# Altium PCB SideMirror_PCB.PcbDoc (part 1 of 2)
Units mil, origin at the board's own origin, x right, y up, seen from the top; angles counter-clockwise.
Board outline 2391.73 x 2364.18 mil, 2 copper layers (Top Layer, Bottom Layer), stack 62 mil thick; 77 components, 73 nets, 281 pads, 345 vias.
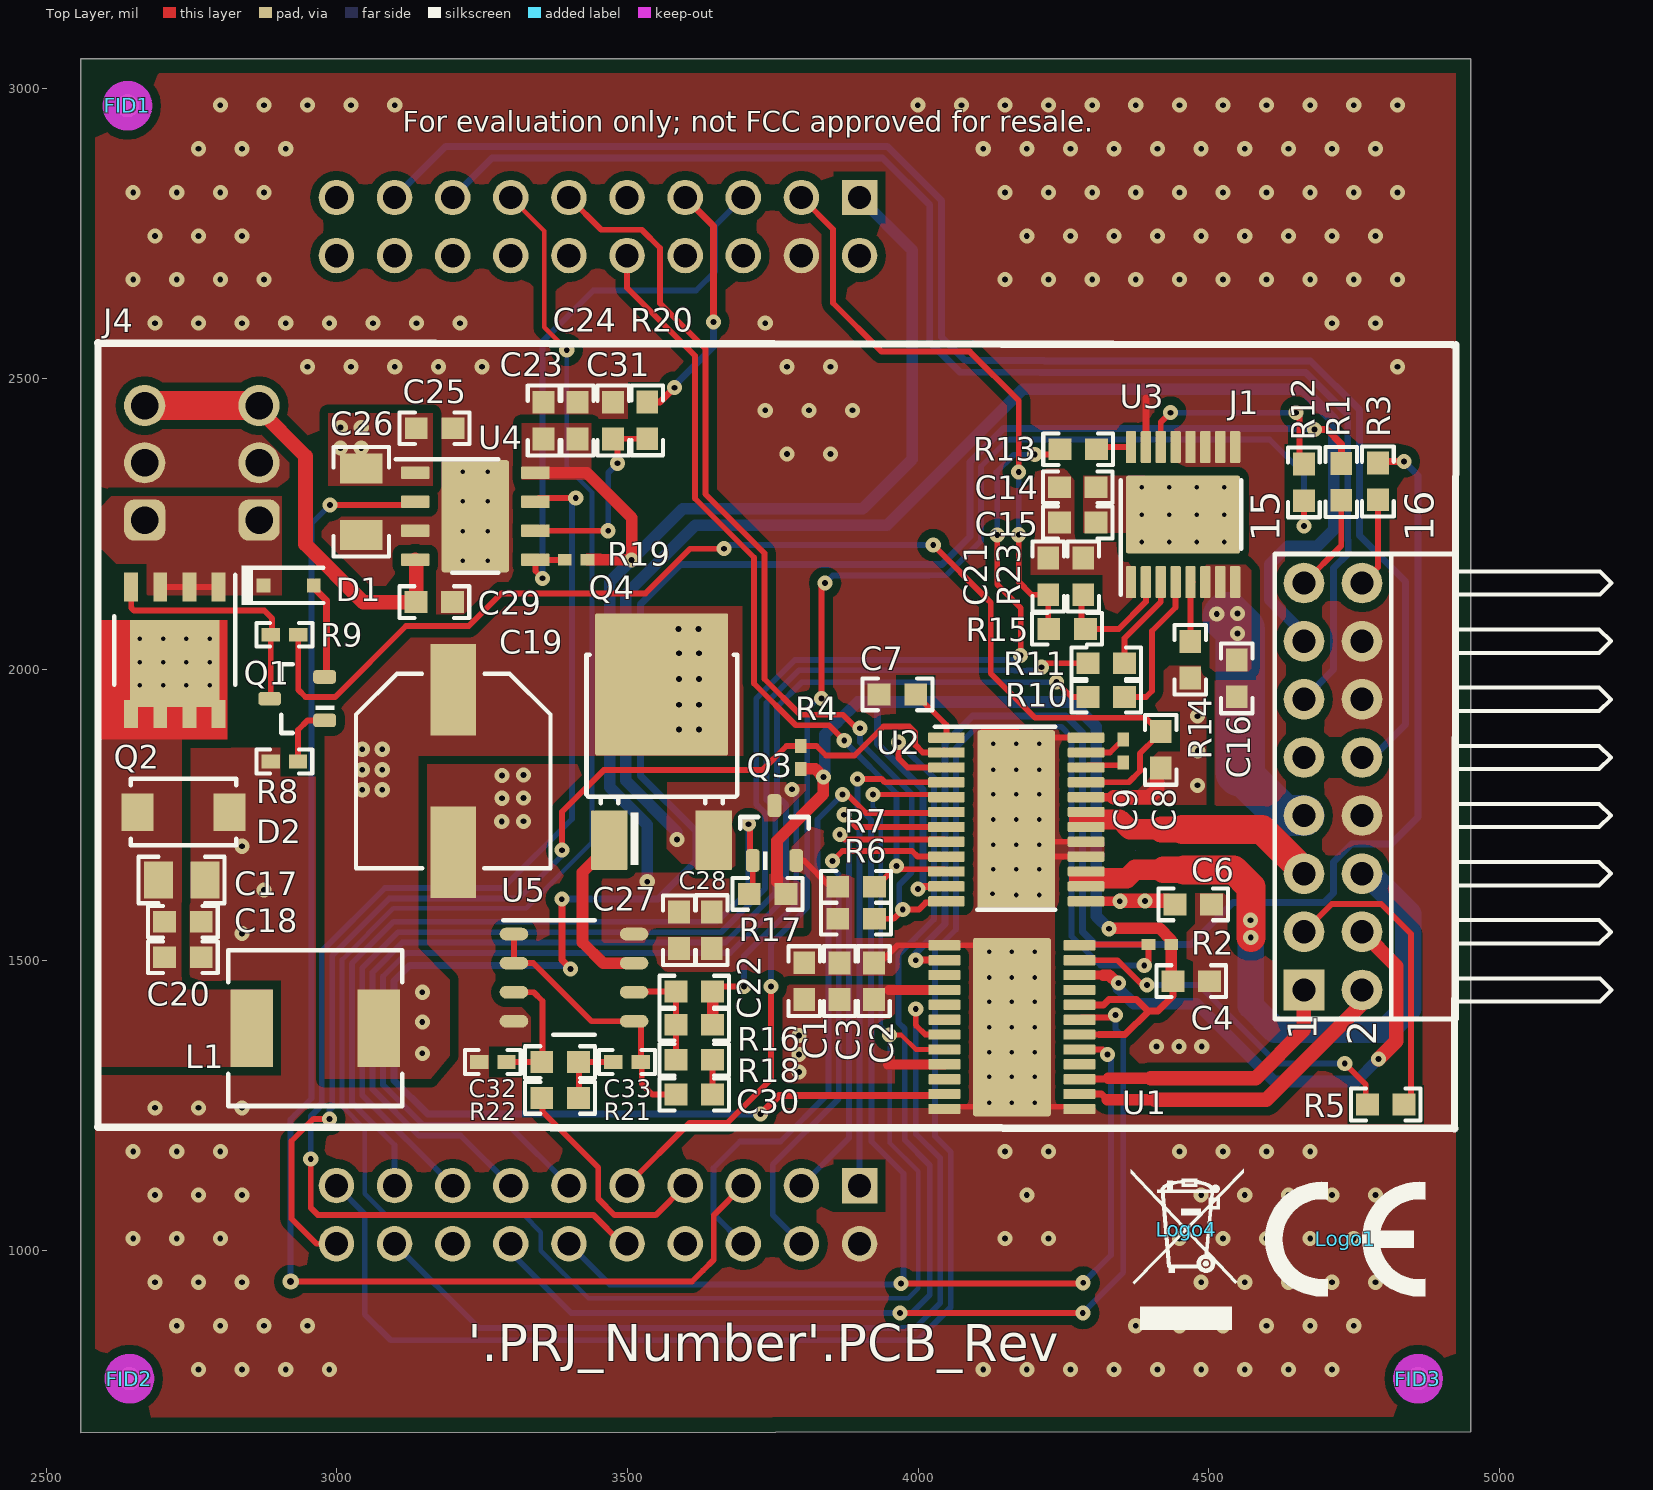
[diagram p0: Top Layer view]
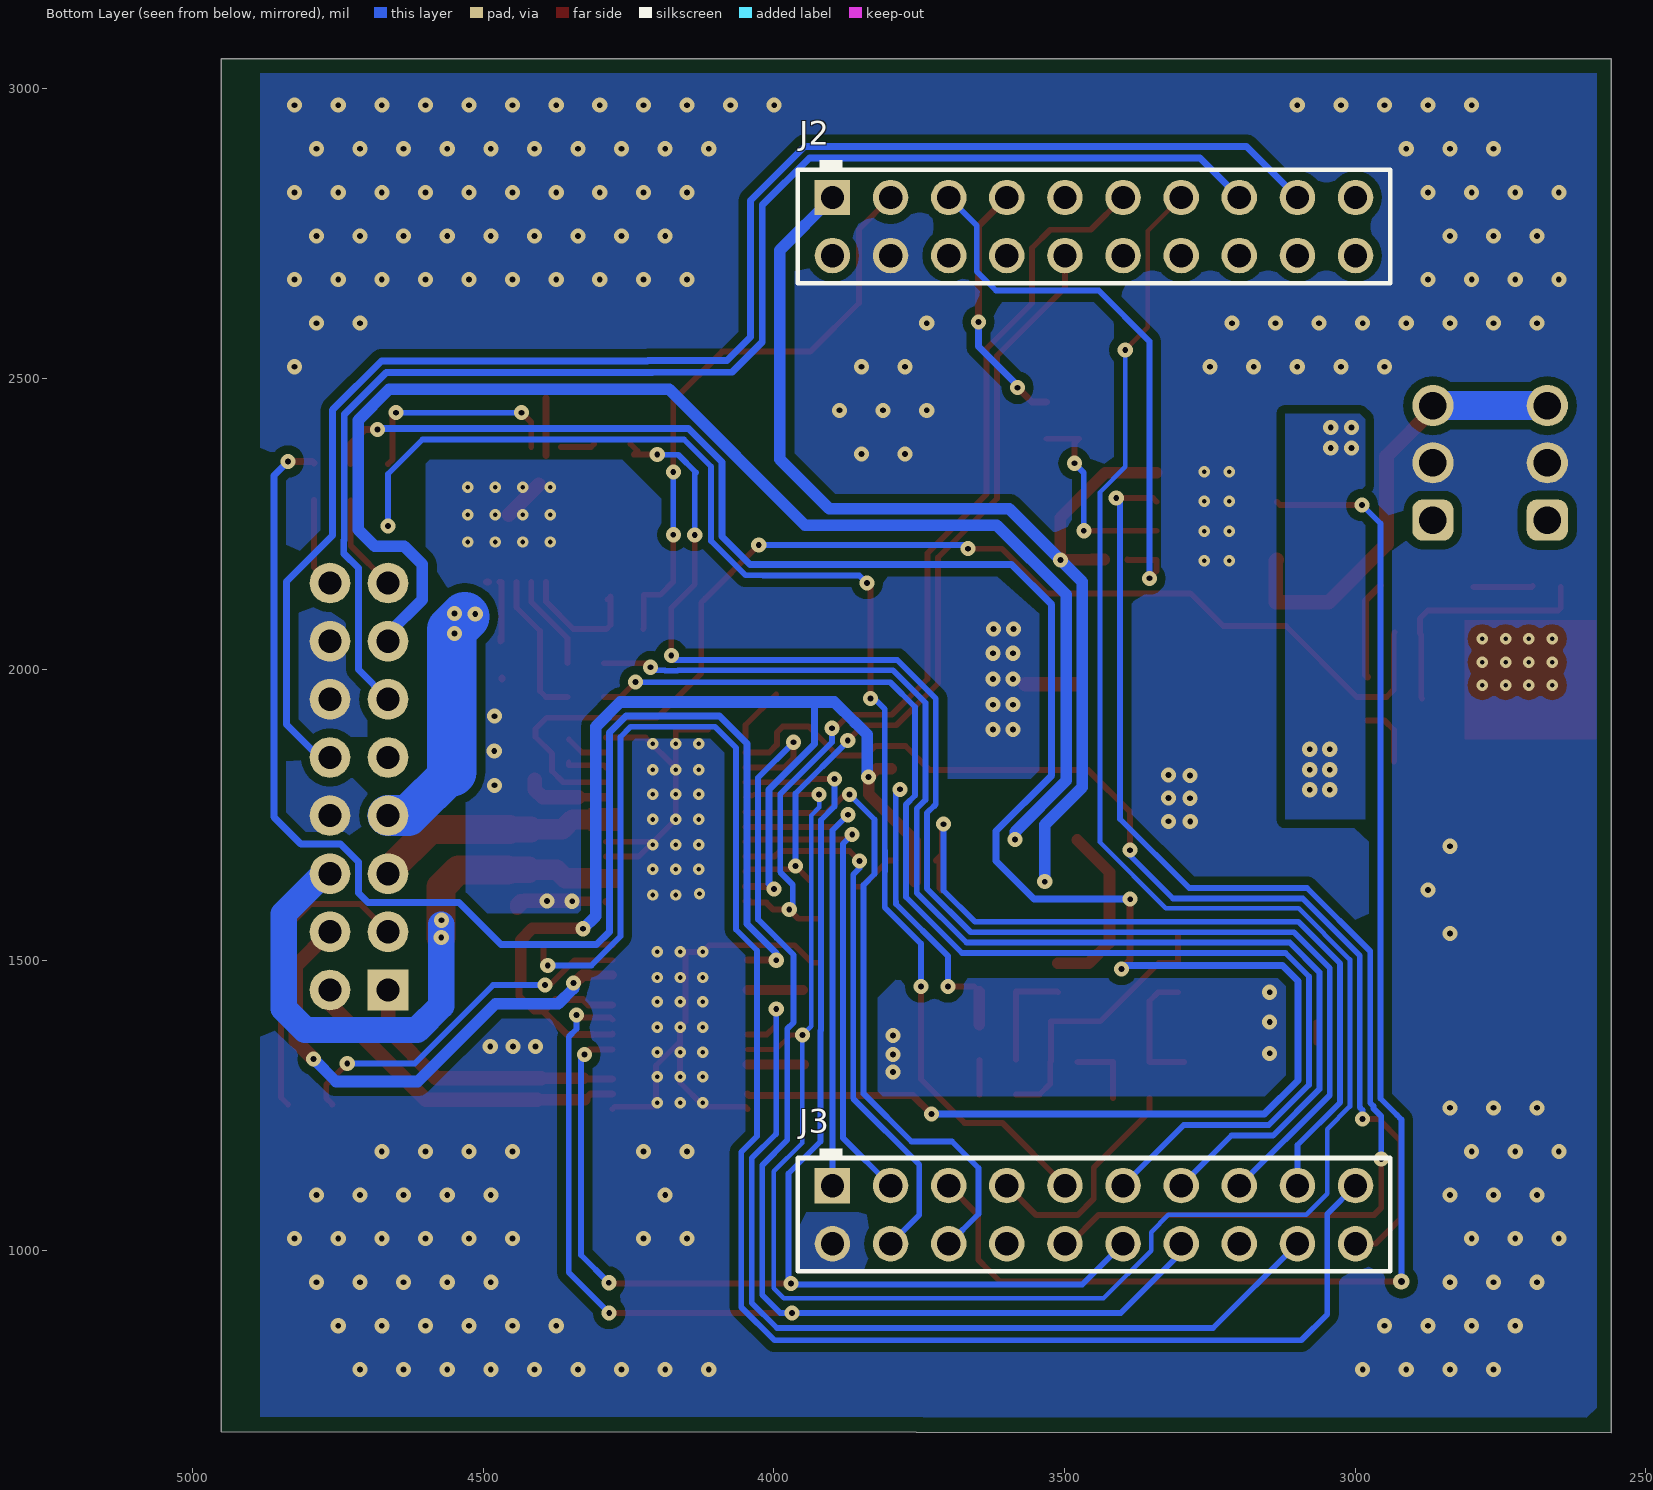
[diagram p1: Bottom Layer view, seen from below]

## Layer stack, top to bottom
Top Solder: solder mask 0.4, Solder Resist, Dk 3.5
Top Layer: signal copper 1.4
Dielectric1: core 59.2, FR-4, Dk 4.8
Bottom Layer: signal copper 1.4
Bottom Solder: solder mask 0.4, Solder Resist, Dk 3.5

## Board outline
2559.06,687 4950.79,688.98 4950.79,3051.18 2559.06,3051.18

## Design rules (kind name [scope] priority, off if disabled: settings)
AcuteAngle [All] p1: minimum=4.50000000000000E+0001 checktracksonly=FALSE
AssemblyTestPointUsage [All] p1: valid=2
BoardOutlineClearance BoardOutlineClearance_MountingHoles [OnCopper and InComponentClass('Mounting Holes')] p1: gap=39.37 ignorepadtopadclearanceinfootprint=FALSE
BoardOutlineClearance BoardOutlineClearance_Poly [OnCopper and IsPoly] p2: gap=25 ignorepadtopadclearanceinfootprint=FALSE
BoardOutlineClearance [OnCopper and Not InComponentClass('Logo') and not InComponentClass('FiducialMark') and not InRegion(1000,500,4000,800) and not InPoly] p3: gap=60 ignorepadtopadclearanceinfootprint=FALSE
Clearance Clearance_Keepouts [((IsTrack Or IsArc) And Not InPoly) And IsFree and IsKeepOut vs ((IsTrack Or IsArc) And Not InPoly) And IsFree and IsKeepOut] p1: gap=0 ignorepadtopadclearanceinfootprint=FALSE
Clearance Clearance_Poly [InPolygon] p2: gap=15 ignorepadtopadclearanceinfootprint=TRUE
Clearance Clearance_FiducialMark [IsKeepOut and InComponentClass('FiducialMark') vs IsPad and InComponentClass('FiducialMark')] p3: gap=0 ignorepadtopadclearanceinfootprint=FALSE
Clearance [All] p4: gap=7.87 ignorepadtopadclearanceinfootprint=TRUE
ComponentClearance ComponentClearance_MountingHoles_FiducialMarks [InComponentClass('Mounting Holes') vs InComponentClass('FiducialMark')] p1: gap=50 collisioncheckmode=3 verticalgap=10 showdistances=FALSE
ComponentClearance ComponentClearance_Shunt [InComponentClass('Header') vs InComponentClass('Shunt')] p2: gap=0 collisioncheckmode=3 verticalgap=0 showdistances=FALSE
ComponentClearance ComponentClearance_Logo [InComponentClass('Logo')] p3: gap=50 collisioncheckmode=3 verticalgap=10 showdistances=FALSE
ComponentClearance ComponentClearance_ScrewToNut [(HasFootprint('NY PMS 440 0025 PH')) vs (HasFootprint('Keystone_1902C'))] p4: gap=5 collisioncheckmode=3 verticalgap=10 showdistances=FALSE
ComponentClearance ComponentClearance_MountingHoles [InComponentClass('Mounting Holes')] p5: gap=250 collisioncheckmode=3 verticalgap=100000 showdistances=FALSE
ComponentClearance ComponentClearance_SmallPassives [HasFootprint('0201*') or HasFootprint('0402*') or HasFootprint('0508') or HasFootprint('0603*') or HasFootprint('0612') or HasFootprint('0805*') or HasFootprint('0815*') or HasFootprint('0830*') or HasFootprint('1206*') or HasFootprint('1210*') or HasFootprint('1808*') or HasFootprint('1812*') or HasFootprint('1825*') or HasFootprint('2010*') or HasFootprint('2220*') or HasFootprint('2225*') or HasFootprint('2512*') or HasFootprint('2728*') or HasFootprint('3518*') vs HasFootprint('0201*') or HasFootprint('0402*') or HasFootprint('0508') or HasFootprint('0603*') or HasFootprint('0612') or HasFootprint('0805*') or HasFootprint('0815*') or HasFootprint('0830*') or HasFootprint('1206*') or HasFootprint('1210*') or HasFootprint('1808*') or HasFootprint('1812*') or HasFootprint('1825*') or HasFootprint('2010*') or HasFootprint('2220*') or HasFootprint('2225*') or HasFootprint('2512*') or HasFootprint('2728*') or HasFootprint('3518*')] p6: gap=14.96 collisioncheckmode=3 verticalgap=10 showdistances=FALSE
ComponentClearance ComponentClearance_THtoSMT [IsThruComponent vs IsSMTComponent] p7: gap=40 collisioncheckmode=3 verticalgap=30 showdistances=FALSE
ComponentClearance ComponentClearance_THtoTH [IsThruComponent vs IsThruComponent] p8: gap=30 collisioncheckmode=3 verticalgap=30 showdistances=FALSE
ComponentClearance [All] p9: gap=30 collisioncheckmode=3 verticalgap=10 showdistances=FALSE
DiffPairsRouting [All] p1: maxlimit=100 minlimit=10 mostfreqgap=10 toplayer_minwidth=15 toplayer_maxwidth=15 toplayer_prefwidth=15 bottomlayer_minwidth=15 bottomlayer_maxwidth=15 bottomlayer_prefwidth=15 maxuncoupledlength=1000
FabricationTestPointUsage TestPointUsage [All] p1: valid=2 allowmultiple=FALSE
FabricationTestpoint Testpoint [All] p1: side=3 testpointundercomponent=TRUE minsize=40 maxsize=100 preferedsize=60 minholesize=0 maxholesize=40 preferedholesize=32 testpointgrid=1 allowsidetop=TRUE allowsidebottom=TRUE usegrid=TRUE gridtolerance=0.01
FanoutControl Fanout_LCC [IsLCC] p1: bgadir=Out bgaviamode=Centered fanoutstyle=Auto fanoutdirection=Alternating viagrid=1 // Fanout_LCC (Default Rule)
FanoutControl Fanout_BGA [IsBGA] p2: bgadir=Out bgaviamode=Centered fanoutstyle=Auto fanoutdirection=Alternating viagrid=1 // Fanout_BGA (Default Rule)
FanoutControl Fanout_Default [All] p4: bgadir=Out bgaviamode=Centered fanoutstyle=Auto fanoutdirection=Alternating viagrid=1 // Fanout_Default (Default Rule)
FanoutControl Fanout_Small [(CompPinCount < 5)] p5: bgadir=Out bgaviamode=Centered fanoutstyle=Auto fanoutdirection=OutThenIn viagrid=1 // Fanout_Small (Default Rule)
HoleSize [All] p1: absolutevalues=TRUE maxlimit=251 minlimit=7.87 maxpercent=80.000 minpercent=20.000
MinimumAnnularRing MinimumAnnularRing_ThermalPadVias [IsVia and InAnyComponent] p1: minimumring=5.91
MinimumAnnularRing [All] p2: minimumring=7.87
MinimumSolderMaskSliver MinimumSolderMaskSliver_Logo [InComponentClass('Logo') vs InComponentClass('Logo')] p1: minsoldermaskwidth=0.7
MinimumSolderMaskSliver [All] p2: minsoldermaskwidth=2.5
PlaneConnect [All] p1: planeconnectstyle=Relief reliefexpansion=10 reliefentries=4 reliefconductorwidth=10 reliefairgap=10
PolygonConnect [All] p1: connectstyle=Direct reliefconductorwidth=10 reliefentries=4 polygonreliefangle="90 Angle" airgapwidth=10
RoutingVias ThermalPadVias [IsVia and InAnyComponent] p1: holewidth=7.87 width=19.68 viastyle="Through Hole" minholewidth=7.87 minwidth=19.68 maxholewidth=12.99 maxwidth=23.62
RoutingVias [All] p2: holewidth=16 width=34 viastyle="Through Hole" minholewidth=7.87 minwidth=26 maxholewidth=40 maxwidth=65
SilkToBoardRegionClearance [Not ((IsComment or IsDesignator) And (Hide <> 'False')) and not InRegion(1000,500,4000,800)] p1:
SilkToSilkClearance SilkToSilkClearance_Pb-FreeLogo [(HasFootprint('Pb-Free_Overlay_Medium') OR HasFootprint('Pb-Free_Overlay_Small')) vs (HasFootprint('Pb-Free_Overlay_Medium') OR HasFootprint('Pb-Free_Overlay_Small'))] p1: silktosilkclearance=0
SilkToSilkClearance [All] p2: silktosilkclearance=2.5
SilkToSolderMaskClearance SilkToComponentPadClearance [(IsPad or IsFill or IsRegion) and InAnycomponent] p1: minsilkscreentomaskgap=5 clearancetoexposedcopper=TRUE
SilkToSolderMaskClearance "Silk to Solder Mask Opening" [All] p2: minsilkscreentomaskgap=3.94 clearancetoexposedcopper=FALSE
SolderMaskExpansion [All] p1: expansion=1.97
UnRoutedNet [All] p1: checkbadconnections=TRUE
Width [All] p1: maxlimit=100 minlimit=6 preferedwidth=10 checkconnectedcopper=TRUE
14 further rules are at their usual default settings.

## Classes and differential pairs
component class AssemblyNote: ZZ1 ZZ2 ZZ3 ZZ4
component class FiducialMark: FID1 FID2 FID3
component class SideMirror_Hardware: FID1 FID2 FID3 J1 J2 J3 Logo1 Logo3 Logo4 ZZ1 ZZ2 ZZ3 ZZ4
component class Header: J1
component class SideMirror_Drivers: C1 C2 C3 C4 C6 C7 C8 C9 R1 R2 R3 R4 R5 R6 R7 U1 U2
component class SideMirror_Logic_TLIN1028: C14 C15 C16 C17 C18 C19 C20 C21 C22 C23 C24 C25 C26 C27 C28 C29 C30 C31 C32 C33 C34 D1 D2 J4 L1 Q1 Q2 Q3 Q4 R8 R9 R10 R11 R12 R13 R14 R15 R16 R17 R18 R19 R20 R21 R22 R23 U3 U4 U5

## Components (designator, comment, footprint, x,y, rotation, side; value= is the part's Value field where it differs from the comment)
C1 "UMK107AB7105KA-T" 0603 3804,1464.01 r90 top value=1uF
C2 "UMK107AB7105KA-T" 0603 3924,1464 r90 top value=1uF
C3 "C0603C104J5RACTU" 0603 3864.81,1464 r270 top value=0.1uF
C4 "GRM188R70J103KA01D" 0603 4470,1464 r0 top value=0.01uF
C6 "C0603C104J5RACTU" 0603 4473.19,1596 r180 top value=0.1uF
C7 "GRM185R60J105KE26D" 0603 3964.5,1957.31 r180 top value=1uF
C8 "UMK107AB7105KA-T" 0603 4417.41,1861.87 r90 top value=1uF
C9 "Capacitor" 0402L 4353,1860 r90 top value=0.047uF
C14 "GRM188R71H104KA93D" 0603 4274.59,2313.57 r180 top value=0.1uF
C15 "GRM188R71H224KAC4D" 0603 4274.59,2253.01 r180 top value=0.22uF
C16 "C0603X223K5RACTU" 0603 4548,1984.8 r270 top value=0.022uF
C17 "GRM21BR71H105KA12L" 0805_HV 2733,1638 r0 top value=1uF
C18 "C1608X7R1H104K080AA" 0603 2735.1,1566 r0 top value=0.1uF
C19 "EEE-FK1J470P" SM_RADIAL_F 3200.18,1825.48 r270 top locked value=47uF
C20 "C1608X7R1H103K080AA" 0603 2735.1,1504.99 r0 top value=0.01uF
C21 "0603ZC101KAT2A" 0603 4224.03,2160.24 r270 top value=100pF
C22 "0603ZC100KAT2A" 0603 3615,1446 r180 top value=10pF
C23 "GRM188Z71A106MA73D" 0603 3355.56,2428.5 r270 top value=10uF
C24 "C0603C104K4RACTU" 0603 3414,2428.5 r270 top value=0.1uF
C25 "C1608X7R1H104K080AA" 0603 3168,2415.1 r180 top value=0.1uF
C26 "CGA5L3X5R1H106M160AB" 1206 3042,2288.78 r270 top value=10uF
C27 "GRM188Z71C475KE21D" 0603 3588.61,1551.69 r270 top value=4.7uF
C28 "GCM188R71C104KA37J" 0603 3645,1551.74 r270 top value=0.1uF
C29 "C0603C221K5RACTU" 0603 3167.72,2116.14 r0 top value=220pF
C30 "GCM188R71H472KA37D" 0603 3615,1269 r180 top value=4700pF
C31 "06033C101KAT2A" 0603 3475.24,2428.5 r270 top value=100pF
C32 "CGA2B3X8R1H103K050BB" 0402 3268.31,1324.79 r180 top value=0.01uF
C33 "GRM155R71H223KA12D" 0402 3499.21,1324.79 r180 top value=0.022uF
D1 "1N4148WS-7-F" SOD-323 2916.86,2144.69 r0 top value=75V
D2 "SMAJ36CA" SMA_Bi 2736,1754.92 r0 top value=36V
FID1 "Fiducial" Fiducial10-20 2639.69,2970 r0 top
FID2 "Fiducial" Fiducial10-20 2643,780 r0 top
FID3 "Fiducial" Fiducial10-20 4860,780 r0 top
J1 "TSW-108-08-G-D-RA" GPSI16 4713.78,1798.82 r90 top locked
J2 "SSQ-110-23-F-D" Samtec_SSQ-110-23-F-D 3449.21,2762.2 r180 bottom locked
J3 "SSQ-110-23-F-D" Samtec_SSQ-110-23-F-D 3449.21,1062.2 r180 bottom locked
J4 "1770898" Phoenix_1770898 2767.72,2355.71 r90 top
L1 "SRP6540-2R2M" SRP6540 2962.51,1383 r0 top value=2.2uH
Logo1 "CE Mark" CE_Mark_5mm 4734.69,1020 r0 top
Logo3 "FCC disclaimer" FCC_disclaimer 2350,3380 r0 top
Logo4 "WEEE logo" WEEE_Minimum 4461,1036.37 r0 top
Q1 "BC846BLT1G" SOT-23 2931.73,1950 r180 top value="65 V"
Q2 "SI7634BDP-T1-E3" PowerPAK_SO-8 2721.1,2032.8 r270 top value=30V
Q3 "FMMT495TA" SOT-23 3752.79,1718.76 r90 top value="150 V"
Q4 "NJVMJD122T4G" DPAK 3558.63,1840.55 r90 top locked value="100 V"
R1 "CRCW0603200RJNEA" 0603 4728,2322.83 r270 top value=200
R2 "Resistor" 0402L 4416,1527 r0 top value=10k
R3 "CRCW0603200RJNEA" 0603 4791,2323.6 r270 top value=200
R4 "Resistor" 0402L 3798,1848.82 r270 top value=10k
R5 "CRCW0603200RJNEA" 0603 4804.45,1251.64 r0 top value=200
R6 "RC0603FR-07680RL" 0603 3893.21,1571.26 r0 top value=680
R7 "RC0603FR-07680RL" 0603 3893.21,1626.26 r0 top value=680
R8 "CRCW040210K0JNED" 0402 2909.62,1842 r180 top value=10k
R9 "CRCW040210K0JNED" 0402 2910,2060 r0 top value=10k
R10 "CRCW060315K0FKEA" 0603 4323.56,1953 r0 top value=15.0k
R11 "CRCW060315K0FKEA" 0603 4323.56,2010.99 r0 top value=15.0k
R12 "CRCW060315K0FKEA" 0603 4663.78,2322 r90 top value=15.0k
R13 "CRCW060315K0FKEA" 0603 4275.29,2379 r0 top value=15.0k
R14 "CRCW060320K0FKEA" 0603 4468.03,2017 r90 top value=20.0k
R15 "CRCW060315K0FKEA" 0603 4256.25,2070 r0 top value=15.0k
R16 "RT0603DRE0710K1L" 0603 3615,1389 r0 top value=10.1k
R17 "RC0603FR-074K7L" 0603 3740.98,1614 r0 top value=4.70k
R18 "CRCW0603499RFKEA" 0603 3615,1328.74 r180 top value=499
R19 "Resistor" 0402L 3411.61,2189.29 r0 top value=10k
R20 "CRCW06031K00FKEA" 0603 3534.12,2428.7 r270 top value=1.00k
R21 "CRCW060378K7FKEA" 0603 3384,1263 r0 top value=78.7k
R22 "CRCW060314K7FKEA" 0603 3383.91,1324.79 r180 top value=14.7k
R23 "ERJ-3EKF1001V" 0603 4284.05,2160.24 r270 top value=1.00k
U1 "DRV8906QPWPRQ1" PWP0024N_N 4161.42,1384.84 r180 top
U2 "DRV8873SPWPRQ1" PWP0024J_M 4168.79,1742.13 r0 top
U3 "TPS1HB16BQPWPTQ1" PWP0016M_N 4455.8,2266.69 r90 top
U4 "TLIN1028DDA" DDA0008G_L 3238.19,2263.78 r0 top
U5 "LM2904QDRQ1" D0008A_L 3408,1470 r0 top
ZZ1 "This Assembly Note is for PCB labels only" AssemblyNoteLabel 185,3938 r0 top
ZZ2 "These assemblies are ESD sensitive, ESD precautions shall be observed." AssemblyNote 185,3829.11 r0 top
ZZ3 "These assemblies must be clean and free from flux and all contaminants. Use of no clean flux is not acceptable." AssemblyNote 185,3740.56 r0 top
ZZ4 "These assemblies must comply with workmanship standards IPC-A-610 Class 2, unless otherwise specified." AssemblyNote 185,3652 r0 top

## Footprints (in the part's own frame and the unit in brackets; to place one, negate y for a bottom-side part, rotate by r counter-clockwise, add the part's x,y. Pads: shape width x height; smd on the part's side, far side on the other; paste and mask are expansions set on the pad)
0402 [mm] "0402 from SM-752 data"
  rect 0.8x0.6 smd: 1(-0.6,0) 2(0.6,0)
  silkscreen extent -1.22,-0.52 1.22,0.52, body extent -0.55,-0.3 0.55,0.3, height 0.6
0402L [mm] "0402 from SM-752 data"
  rect 0.6x0.5 smd: 1(-0.5,0) 2(0.5,0)
  body extent -0.55,-0.3 0.55,0.3, height 0.6
0603 [mm] "0603 from SM-752 data"
  rect 1x0.95 smd: 1(-0.8,0) 2(0.8,0)
  silkscreen extent -1.52,-0.69 1.52,0.69, body extent -0.87,-0.47 0.87,0.47, height 1
0805_HV [mil] "0805 with 30mil clearance between pads"
  rect 50x63 smd: 1(-40,0) 2(40,0)
  silkscreen extent -74,-40 74,40, body extent -43,-29 43,29, height 57
1206 [mm] "1206 from SM-752 data"
  rect 1.3x1.85 smd: 1(-1.45,0) 2(1.45,0)
  silkscreen extent -2.4,-1.21 2.4,1.21, body extent -1.7,-0.9 1.7,0.9, height 1.35
AssemblyNote [mil] "Assembly Note"
AssemblyNoteLabel [mil] "Assembly Note for PCB Labels"
CE_Mark_5mm [mil] "Minimum text height for CE Mark"
  silkscreen extent -138,-98 138,98
D0008A_L [mm] "SOIC, 8-Leads, Body 4.9x3.9mm, Pitch 1.27mm, IPC High Density"
  oval 1.25x0.55 smd: 1(-2.625,1.905) 2(-2.625,0.635) 3(-2.625,-0.635) 4(-2.625,-1.905) 5(2.625,-1.905) 6(2.625,-0.635) 7(2.625,0.635) 8(2.625,1.905)
  silkscreen extent -3.1,-2.5 0.9,2.5, body extent -3,-2.45 3,2.45, height 1.63
DDA0008G_L [mm] "SOIC, 8-Leads, Body 4.9x3.9mm, Pitch 1.27mm, Exposed Pad, IPC High Density"
  rrect18% 1.25x0.55 smd: 1(-2.625,1.905) 2(-2.625,0.635) 3(-2.625,-0.635) 4(-2.625,-1.905) 5(2.625,-1.905) 6(2.625,-0.635) 7(2.625,0.635) 8(2.625,1.905)
  rrect7% 2.95x4.9 smd paste-1.5 mask-1.5: 9(0,0)
  rrect4% 2.29x3.1 on Top Solder: 9(0,0)
  rrect4% 2.29x3.1 on Top Paste: 9(0,0)
  silkscreen extent -3.47,-2.48 1,2.5, body extent -2.98,-2.45 2.98,2.45, height 1.55
DPAK [mm] "D-PAK, 3-Pads, Body 6.22x6.73mm (max), TO-252AA using nominal STEP model"
  rrect6% 2.6x1.6 smd: 1(-3.4,2.28) 3(-3.4,-2.28)
  rrect2% 6.2x5.8 smd paste-2.9: 4(3.4,0)
  silkscreen extent -4.5,-3.3 4.7,3.28, body extent -3.86,-3.29 5.84,3.29, height 2.48
FCC_disclaimer [mil]
Fiducial10-20 [mm]
  round 1 smd mask+0.5: 1(0,0)
  Top Layer keep-out circle w1.178: c0,0 r0.5
GPSI16 [mil] "Samtec Right Angle Header, pins flipped from convention"
  rect 70x70 hole 40: 1(-350,50)
  round 70 hole 40: 2(-350,-50) 3(-250,50) 4(-250,-50) 5(-150,50) 6(-150,-50) 7(-50,50) 8(-50,-50) 9(50,50) 10(50,-50) 11(150,50) 12(150,-50) 13(250,50) 14(250,-50) 15(350,50) 16(350,-50)
  silkscreen extent -400,-479 400,100, body extent -400,-440 400,63, height 219
Phoenix_1770898 [mm] "Terminal Block, 3 Pos, 2.5mm, R/A, TH"
  rrect50% 1.8x1.8 hole 1.2: 1(-2.5,-2.5) 1(-2.5,2.5)
  round 1.8 hole 1.2: 2(0,2.5) 2(0,-2.5) 3(2.5,-2.5) 3(2.5,2.5)
  body extent -3.1,-4.7 5,5.3, height 5
PowerPAK_SO-8 [mil] "Vishay PowerPAK SO-8, Body 5.3x6.0mm (max), Pitch 1.27mm, IPC Medium Density"
  rect 50x24 smd mask+2.99: 1(-109.5,75) 2(-109.5,25) 3(-109.5,-25) 4(-109.5,-75)
  rect 48x24 smd mask+2.99: 5(109.5,-75) 8(109.5,75)
  rect 48x24 smd paste-12 mask+2.99: 6(109.5,-25) 7(109.5,25)
  rect 150x154 smd paste-75 mask+2.99: 9(22.5,0)
  silkscreen extent -130,-104 59,104, body extent -121,-102 121,102, height 43
PWP0016M_N [mm] "TSOP, 16-Leads, Body 5x4.4mm, Pitch 0.65mm, Thermal Pad 2.41x3.29 mm, IPC Medium Density"
  rrect22% 1.4x0.45 smd: 1(-2.95,2.275) 2(-2.95,1.625) 3(-2.95,0.975) 4(-2.95,0.325) 5(-2.95,-0.325) 6(-2.95,-0.975) 7(-2.95,-1.625) 8(-2.95,-2.275) 9(2.95,-2.275) 10(2.95,-1.625) 11(2.95,-0.975) 12(2.95,-0.325) 13(2.95,0.325) 14(2.95,0.975) 15(2.95,1.625) 16(2.95,2.275)
  rrect6% 3.4x5 smd paste-1.7 mask-1.7: 17(0,0)
  rrect4% 2.78x3.37 on Top Solder: 17(0,0)
  rrect4% 2.78x3.37 on Top Paste: 17(0,0)
  silkscreen extent -3.5,-2.55 1.5,2.73, body extent -3.21,-2.5 3.21,2.5, height 0.99
PWP0024J_M [mm] "TSOP, 24-Leads, Body 7.9x4.5mm (max), Pitch 0.65mm, IPC Low Density"
  rrect22% 1.6x0.45 smd: 1(-3.05,3.575) 2(-3.05,2.925) 3(-3.05,2.275) 4(-3.05,1.625) 5(-3.05,0.975) 6(-3.05,0.325) 7(-3.05,-0.325) 8(-3.05,-0.975) 9(-3.05,-1.625) 10(-3.05,-2.275) 11(-3.05,-2.925) 12(-3.05,-3.575) 13(3.05,-3.575) 14(3.05,-2.925) 15(3.05,-2.275) 16(3.05,-1.625) 17(3.05,-0.975) 18(3.05,-0.325) 19(3.05,0.325) 20(3.05,0.975) 21(3.05,1.625) 22(3.05,2.275) 23(3.05,2.925) 24(3.05,3.575)
  rrect6% 3.4x7.8 smd paste-2 mask-2: 25(0,0)
  rrect3% 3.2x5.26 on Top Solder mask+0.085: 25(0,0)
  rrect3% 3.2x5.26 on Top Paste mask+0.085: 25(0,0)
  silkscreen extent -3.55,-3.95 1.7,4.05, body extent -3.21,-3.9 3.21,3.9, height 1.2
PWP0024N_N [mm] "TSOP-24"
  rrect22% 1.4x0.45 smd: 1(-2.95,3.575) 2(-2.95,2.925) 3(-2.95,2.275) 4(-2.95,1.625) 5(-2.95,0.975) 6(-2.95,0.325) 7(-2.95,-0.325) 8(-2.95,-0.975) 9(-2.95,-1.625) 10(-2.95,-2.275) 11(-2.95,-2.925) 12(-2.95,-3.575) 13(2.95,-3.575) 14(2.95,-2.925) 15(2.95,-2.275) 16(2.95,-1.625) 17(2.95,-0.975) 18(2.95,-0.325) 19(2.95,0.325) 20(2.95,0.975) 21(2.95,1.625) 22(2.95,2.275) 23(2.95,2.925) 24(2.95,3.575)
  rrect6% 3.4x7.8 smd paste-2 mask-2: 25(0,0)
  body extent -3.21,-3.9 3.21,3.9, height 1.2
Samtec_SSQ-110-23-F-D [mm] "Receptacle, 2.54mm, 10x2, TH"
  rect 1.55x1.55 hole 1.02: 1(-11.43,1.27)
  round 1.55 hole 1.02: 2(-11.43,-1.27) 3(-8.89,1.27) 4(-8.89,-1.27) 5(-6.35,1.27) 6(-6.35,-1.27) 7(-3.81,1.27) 8(-3.81,-1.27) 9(-1.27,1.27) 10(-1.27,-1.27) 11(1.27,1.27) 12(1.27,-1.27) 13(3.81,1.27) 14(3.81,-1.27) 15(6.35,1.27) 16(6.35,-1.27) 17(8.89,1.27) 18(8.89,-1.27) 19(11.43,1.27) 20(11.43,-1.27)
  silkscreen extent -12.95,-2.48 12.95,2.9, body extent -12.95,-2.48 12.95,2.48, height 8.51
SM_RADIAL_F [mm] "8 x 10.2mm:  Panasonic F"
  rect 4x2 smd: 1(-3.55,0) 2(3.55,0)
  silkscreen extent -4.25,-4.25 4.25,4.25, body extent -4.25,-4.25 4.25,4.25, height 10.5
SMA_Bi [mm] "SMD, 2-Leads, Body 4.275x2.575mm"
  rect 1.4x1.64 smd: 1(-2.015,0) 2(2.015,0)
  silkscreen extent -2.3,-1.45 2.3,1.45, body extent -2.52,-1.45 2.52,1.45, height 2.65
SOD-323 [mm] "NXP recommended land pattern"
  rect 0.6x0.6 smd paste-0.05: 1(-1.1,0) 2(1.1,0)
  silkscreen extent -2.06,-0.86 1.52,0.86, body extent -1.3,-0.67 1.3,0.68, height 1.1
SOT-23 [mm] "SOT23, 3-Leads, Body 2.9x1.3mm, Pitch 0.95mm, Lead Span 2.5mm, IPC Medium Density"
  rrect50% 1x0.6 smd: 1(-1.2,0.95) 2(-1.2,-0.95) 3(1.2,0)
  silkscreen extent -1.62,-1.5 0.7,1.5, body extent -1.16,-1.45 1.21,1.45, height 1
SRP6540 [mm] "Bourns"
  rect 1.85x3.4 smd: 1(-2.775,0) 2(2.775,0)
  silkscreen extent -3.8,-3.4 3.8,3.4, body extent -3.75,-3.35 3.75,3.35, height 4
WEEE_Minimum [mil] "WEEElie bin"
  silkscreen extent -95,-172 99,104

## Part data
C1 C2 C8: library part CMP-0007508-5, "CAP, CERM, 1 uF, 50 V, +/- 10%, X7R, 0603", Cap_Case=0603, Manufacturer="Taiyo Yuden", Supplier Part Number 1=587-3247-1-ND, TempCo=X7R, Tolerance_%=10%, Value1=Unknown, Value2=50V, ValueDisplayed=1uF
C3 C6: library part CMP-0006858-4, "CAP, CERM, 0.1 uF, 50 V, +/- 5%, X7R, 0603", Cap_Case=0603, Manufacturer=Kemet, Supplier Part Number 1=399-7844-1-ND, TempCo=X7R, Tolerance_%=5%, Value1=Unknown, Value2=50V, ValueDisplayed=0.1uF
C4: library part CMP-0007358-5, "CAP, CERM, 0.01 uF, 6.3 V, +/- 10%, X7R, 0603", Cap_Case=0603, Manufacturer=MuRata, Supplier Part Number 1=GRM188R70J103KA01D-ND, TempCo=X7R, Tolerance_%=10%, Value1=Unknown, Value2=6.3V, ValueDisplayed=0.01uF
C7: library part CMP-0007155-1, "CAP, CERM, 1 uF, 6.3 V, +/- 10%, X5R, 0603", Cap_Case=0603, Manufacturer=MuRata, Supplier Part Number 1=81-GRM185R60J105KE26, TempCo=X5R, Tolerance_%=10%, Value1=Unknown, Value2=6.3V, ValueDisplayed=1uF
C9: library part CMP-0006280-2, "CAP, CERM, 0.047 uF, 50 V, +/- 10%, X5R, 0402", Cap_Case=0402, Manufacturer=TDK, PartNumber=C1005X5R1H473K050BB, Supplier Part Number 1=445-7382-1-ND, TempCo=X5R, Tolerance_%=10%, Value1="0.06407 ohm", Value2=50V, ValueDisplayed=0.047uF
C14: library part CMP-0007434-4, "CAP, CERM, 0.1 uF, 50 V, +/- 10%, X7R, 0603", Cap_Case=0603, Manufacturer=MuRata, Supplier Part Number 1=490-1519-1-ND, TempCo=X7R, Tolerance_%=10%, Value1=Unknown, Value2=50V, ValueDisplayed=0.1uF
C15: library part CMP-0007445-4, "CAP, CERM, 0.22 uF, 50 V, +/- 10%, X7R, 0603", Cap_Case=0603, Manufacturer=MuRata, Supplier Part Number 1=490-12546-1-ND, TempCo=X7R, Tolerance_%=10%, Value1=Unknown, Value2=50V, ValueDisplayed=0.22uF
C16: library part CMP-0006984-4, "CAP, CERM, 0.022 uF, 50 V, +/- 10%, X7R, 0603", Cap_Case=0603, Manufacturer=Kemet, Supplier Part Number 1=399-5340-1-ND, TempCo=X7R, Tolerance_%=10%, Value1=Unknown, Value2=50V, ValueDisplayed=0.022uF
C17: library part CMP-0008350-2, "CAP, CERM, 1 uF, 50 V, +/- 10%, X7R, 0805", Cap_Case=0805, Manufacturer=MuRata, Supplier Part Number 1=490-4736-1-ND, TempCo=X7R, Tolerance_%=10%, Value1=Unknown, Value2=50V, ValueDisplayed=1uF
C18 C25: library part CMP-0007044-5, "CAP, CERM, 0.1 uF, 50 V, +/- 10%, X7R, 0603", Cap_Case=0603, Manufacturer=TDK, Supplier Part Number 1=445-1314-1-ND, TempCo=X7R, Tolerance_%=10%, Value1="0.0296 ohm", Value2=50V, ValueDisplayed=0.1uF
C19: library part CMP-0011192-2, "CAP, AL, 47 uF, 63 V, +/- 20%, 0.65 ohm, AEC-Q200 Grade 2, SMD", Cap_Case=F, Manufacturer=Panasonic, Supplier Part Number 1=PCE3823CT-ND, Tolerance_%=20%, Value1="0.65 ohm", Value2=63V, ValueDisplayed=47uF
C20: library part CMP-0007043-4, "CAP, CERM, 0.01 uF, 50 V, +/- 10%, X7R, 0603", Cap_Case=0603, Manufacturer=TDK, Supplier Part Number 1=445-1311-1-ND, TempCo=X7R, Tolerance_%=10%, Value1="0.0539 ohm", Value2=50V, ValueDisplayed=0.01uF
C21: library part CMP-0006812-4, "CAP, CERM, 100 pF, 10 V, +/- 10%, X7R, 0603", Cap_Case=0603, Manufacturer=AVX, Supplier Part Number 1=0603ZC101KAT2A-ND, TempCo=X7R, Tolerance_%=10%, Value1=Unknown, Value2=10V, ValueDisplayed=100pF
C22: library part CMP-0006811-2, "CAP, CERM, 10 pF, 10 V, +/- 10%, X7R, 0603", Cap_Case=0603, Manufacturer=AVX, Supplier Part Number 1=0603ZC100KAT2A-ND, TempCo=X7R, Tolerance_%=10%, Value1=Unknown, Value2=10V, ValueDisplayed=10pF
C23: library part CMP-0007497-5, "CAP, CERM, 10 uF, 10 V, +/- 20%, X7R, 0603", Cap_Case=0603, Manufacturer=MuRata, Supplier Part Number 1=81-GRM188Z71A106MA3D, TempCo=X7R, Tolerance_%=20%, Value1=Unknown, Value2=10V, ValueDisplayed=10uF
C24: library part CMP-0006860-5, "CAP, CERM, 0.1 uF, 16 V, +/- 10%, X7R, 0603", Cap_Case=0603, Manufacturer=Kemet, Supplier Part Number 1=399-1096-1-ND, TempCo=X7R, Tolerance_%=10%, Value1=Unknown, Value2=16V, ValueDisplayed=0.1uF
C26: library part CMP-0008785-1, "CAP, CERM, 10 uF, 50 V, +/- 20%, X5R, AEC-Q200 Grade 3, 1206", Cap_Case=1206, Manufacturer=TDK, Supplier Part Number 1=445-12883-1-ND, TempCo=X5R, Tolerance_%=20%, Value1=Unknown, Value2=50V, ValueDisplayed=10uF
C27: library part CMP-0064936-2, "CAP, CERM, 4.7 uF, 16 V,+/- 10%, X7R, 0603", Cap_Case=0603, Manufacturer=MuRata, TempCo=X7R, Tolerance_%=10%, Value1=Unknown, Value2=16V, ValueDisplayed=4.7uF
C28: library part CMP-0007135-2, "CAP, CERM, 0.1 uF, 16 V, +/- 10%, X7R, AEC-Q200 Grade 1, 0603", Cap_Case=0603, Manufacturer=MuRata, Supplier Part Number 1=490-8015-1-ND, TempCo=X7R, Tolerance_%=10%, Value1=Unknown, Value2=16V, ValueDisplayed=0.1uF
C29: library part CMP-0006895-4, "CAP, CERM, 220 pF, 50 V, +/- 10%, X7R, 0603", Cap_Case=0603, Manufacturer=Kemet, Supplier Part Number 1=399-1071-1-ND, TempCo=X7R, Tolerance_%=10%, Value1=Unknown, Value2=50V, ValueDisplayed=220pF
C30: library part CMP-0007146-2, "CAP, CERM, 4700 pF, 50 V, +/- 10%, X7R, AEC-Q200 Grade 1, 0603", Cap_Case=0603, Manufacturer=MuRata, Supplier Part Number 1=490-4932-1-ND, TempCo=X7R, Tolerance_%=10%, Value1=Unknown, Value2=50V, ValueDisplayed=4700pF
C31: library part CMP-0006751-4, "CAP, CERM, 100 pF, 25 V, +/- 10%, X7R, 0603", Cap_Case=0603, Manufacturer=AVX, Supplier Part Number 1=55J3899, TempCo=X7R, Tolerance_%=10%, Value1=Unknown, Value2=25V, ValueDisplayed=100pF
C32: library part CMP-0078224-1, "CAP, CERM, 0.01 µF, 50 V,+/- 10%, X8R, AEC-Q200 Grade 0, 0402", Cap_Case=0402, Manufacturer=TDK, Supplier Part Number 1=445-12303-1-ND, TempCo=X8R, Tolerance_%=10%, Value2=50V, ValueDisplayed=0.01µF
C33: library part CMP-0006684-1, "CAP, CERM, 0.022 uF, 50 V, +/- 10%, X7R, 0402", Cap_Case=0402, Manufacturer=MuRata, Supplier Part Number 1=490-3884-1-ND, TempCo=X7R, Tolerance_%=10%, Value1=Unknown, Value2=50V, ValueDisplayed=0.022uF
D1: library part CMP-0079597-1, "Diode, Switching, 75 V, 0.15 A, AEC-Q101, SOD-323", Manufacturer="Diodes Inc.", Supplier Part Number 1=1N4148WS-FDICT-ND, Value1=0.15A, Value2=1.25V
D2: library part CMP-0085017-1, "Diode, TVS, Bi, 36 V, 58.1 Vc, 400 W, 6.9 A, SMA (non-polarized)", Manufacturer=Littelfuse, Value1=58.1V
FID1 FID2 FID3: library part CMP-0077181-1, "Fiducial mark.  There is nothing to buy or mount.", Manufacturer=N/A
J1: library part CMP-0075420-1, "Header, 100mil, 8x2, Gold, R/A, TH", Color=Black, Current_A=6.3A, Manufacturer=Samtec, Supplier Part Number 1=SAM1037-08-ND, Voltage_V=550V
J2 J3: library part CMP-0055675-1, "Receptacle, 2.54mm, 10x2, Gold, TH", Color=Black, Current_A=6.3A, Manufacturer=Samtec, Voltage_V=550V
J4: library part CMP-0084507-1, "Terminal Block, 3 Pos, 2.5mm, R/A, TH", Color=Black, Current_A=6A, Manufacturer="Phoenix Contact", Voltage_V=160V
L1: library part CMP-0056962-1, "Inductor, Shielded, Ferrite, 2.2 uH, 9 A, 0.0155 ohm, SMD", Manufacturer=Bourns, Supplier Part Number 1=652-SRP6540-2R2M, Value1="0.0155 ohm", Value2=9A, ValueDisplayed=2.2uH
Logo1: library part CMP-0074844-1
Logo3: library part CMP-0074847-1, "FCC_disclaimer"
Logo4: library part CMP-0074769-1
Q1: library part CMP-0000375-2, "Transistor, NPN, 65 V, 0.1 A, SOT-23", Manufacturer="ON Semiconductor", Supplier Part Number 1=BC846BLT1GOSCT-ND, Value1="0.1 A", Value2=450
Q2: library part CMP-0082509-1, "MOSFET, N-CH, 30 V, 40 A, PowerPAK SO-8", Alternate Manufacturer=None, Manufacturer=Vishay-Siliconix, Supplier Part Number 1=SI7634BDP-T1-E3-ND, Value1="0.007 ohm", Value2="45.5 nC"
Q3: library part CMP-0074710-1, "Transistor, NPN, 150 V, 1 A, AEC-Q101, SOT-23", Manufacturer="Diodes Inc.", Supplier Part Number 1=FMMT495CT-ND, Value1="1 A", Value2=300.0
Q4: library part CMP-0077549-1, "Transistor, NPN, 100 V, 8 A, AEC-Q101, DPAK", Manufacturer="ON Semiconductor", Supplier Part Number 1=NJVMJD122T4G-VF01OSCT-ND, Value1="8 A"
R1 R3 R5: library part CMP-0025752-4, "RES, 200, 5%, 0.1 W, AEC-Q200 Grade 0, 0603", Manufacturer=Vishay-Dale, Power_W=100mW, Supplier Part Number 1=541-200GCT-ND, TempCo="200 ppm/C", Tolerance_%=5%, Value2=0.1W, Value_Code=200R, ValueDisplayed=200
R2 R4 R19: library part CMP-0026825-5, "RES, 10 k, 5%, 0.063 W, AEC-Q200 Grade 0, 0402", Manufacturer=Vishay-Dale, PartNumber=CRCW040210K0JNED, Power_W=63mW, Supplier Part Number 1=541-10KJCT-ND, TempCo="200 ppm/C", Tolerance_%=5%, Value2=0.063W, Value_Code=10k0, ValueDisplayed=10k
R6 R7: library part CMP-0023235-5, "RES, 680, 1%, 0.1 W, 0603", Manufacturer=Yageo, Power_W=100mW, Supplier Part Number 1=311-680HRCT-ND, TempCo="100 ppm/C", Tolerance_%=1%, Value2=0.1W, Value_Code=680R, ValueDisplayed=680
R8 R9: library part CMP-0026825-4, "RES, 10 k, 5%, 0.063 W, 0402", Manufacturer=Vishay-Dale, Power_W=63mW, Supplier Part Number 1=541-10KJCT-ND, TempCo="200 ppm/C", Tolerance_%=5%, Value2=0.063W, Value_Code=10k0, ValueDisplayed=10k
R10 R11 R12 R13 R15: library part CMP-0022066-4, "RES, 15.0 k, 1%, 0.1 W, AEC-Q200 Grade 0, 0603", Manufacturer=Vishay-Dale, Power_W=100mW, Supplier Part Number 1=541-15.0KHCT-ND, TempCo="100 ppm/C", Tolerance_%=1%, Value2=0.1W, Value_Code=15k0, ValueDisplayed=15.0k
R14: library part CMP-0022204-4, "RES, 20.0 k, 1%, 0.1 W, AEC-Q200 Grade 0, 0603", Manufacturer=Vishay-Dale, Power_W=100mW, Supplier Part Number 1=541-20.0KHCT-ND, TempCo="100 ppm/C", Tolerance_%=1%, Value2=0.1W, Value_Code=20k0, ValueDisplayed=20.0k
R16: library part CMP-0024579-1, "RES, 10.1 k, 0.5%, 0.1 W, 0603", Manufacturer="Yageo America", Power_W=100mW, TempCo="50 ppm/C", Tolerance_%=0.5%, Value2=0.1W, Value_Code=10k1, ValueDisplayed=10.1k
R17: library part CMP-0023153-2, "RES, 4.70 k, 1%, 0.1 W, 0603", Manufacturer="Yageo America", Power_W=100mW, Supplier Part Number 1=311-4.70KHRCT-ND, TempCo="200 ppm/C", Tolerance_%=1%, Value2=0.1W, Value_Code=4k70, ValueDisplayed=4.70k
R18: library part CMP-0022446-3, "RES, 499, 1%, 0.1 W, 0603", Manufacturer=Vishay-Dale, Power_W=100mW, Supplier Part Number 1=541-499HCT-ND, TempCo="100 ppm/C", Tolerance_%=1%, Value2=0.1W, Value_Code=499R, ValueDisplayed=499
R20: library part CMP-0022109-5, "RES, 1.00 k, 1%, 0.1 W, AEC-Q200 Grade 0, 0603", Manufacturer=Vishay-Dale, Power_W=100mW, Supplier Part Number 1=541-1.00KHCT-ND, TempCo="100 ppm/C", Tolerance_%=1%, Value2=0.1W, Value_Code=1k00, ValueDisplayed=1.00k
R21: library part CMP-0022597-4, "RES, 78.7 k, 1%, 0.1 W, AEC-Q200 Grade 0, 0603", Manufacturer=Vishay-Dale, Power_W=100mW, Supplier Part Number 1=541-78.7KHCT-ND, TempCo="100 ppm/C", Tolerance_%=1%, Value2=0.1W, Value_Code=78k7, ValueDisplayed=78.7k
R22: library part CMP-0022056-4, "RES, 14.7 k, 1%, 0.1 W, AEC-Q200 Grade 0, 0603", Manufacturer=Vishay-Dale, Power_W=100mW, Supplier Part Number 1=541-14.7KHCT-ND, TempCo="100 ppm/C", Tolerance_%=1%, Value2=0.1W, Value_Code=14k7, ValueDisplayed=14.7k
R23: library part CMP-0022680-4, "RES, 1.00 k, 1%, 0.1 W, 0603", Manufacturer=Panasonic, Power_W=100mW, Supplier Part Number 1=P1.00KHCT-ND, TempCo="100 ppm/C", Tolerance_%=1%, Value2=0.1W, Value_Code=1k00, ValueDisplayed=1.00k
U1: library part CMP-0860359-2, "DRV8906QPWPRQ1, PWP0024N (HTSSOP-24)", Alternate Manufacturer="Texas Instruments", Alternate PartNumber=DRV8906QPWTRQ1
U2: library part CMP-0065213-5, "Automotive H-Bridge Motor Driver, PWP0024J (TSSOP-24)", Alternate Manufacturer="Texas Instruments", Rating=Automotive
U3: library part CMP-0080493-1, "TPS1HB16BQPWPTQ1, PWP0016M (TSSOP-16)", Alternate Manufacturer="Texas Instruments", Alternate PartNumber=TPS1HB16BQPWPRQ1
U4: library part CMP-0074642-4, "Automotive Local Interconnect Network Transceiver, DDA0008G (SOIC-8)", Alternate Manufacturer="Texas Instruments"
U5: library part CMP-0075745-1, "Automotive Catalog Dual Operational Amplifier, D0008A (SOIC-8)", Alternate Manufacturer="Texas Instruments"
ZZ1: library part CMP-0003616-3
ZZ2: library part CMP-0077236-1
ZZ3: library part CMP-0077237-1
ZZ4: library part CMP-0077238-1

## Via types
v1: diameter 26, hole 10, Top Layer to Bottom Layer, tented top, 270 vias
v2: diameter 19.68, hole 7.87, Top Layer to Bottom Layer, 46 vias
v3: diameter 19.68, hole 7.87, Top Layer to Bottom Layer, tented both sides, 28 vias
v4: diameter 28, hole 12, Top Layer to Bottom Layer, 1 vias

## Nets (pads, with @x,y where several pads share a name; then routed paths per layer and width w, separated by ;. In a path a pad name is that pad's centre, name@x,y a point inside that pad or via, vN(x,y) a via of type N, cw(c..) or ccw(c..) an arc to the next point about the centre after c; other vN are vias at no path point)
3.3V: C4.1 C23.2 C24.2 C27.1 C28.1 J2.1 R2.2 R4.2 R17.2 R19.2 U1.6 U1.8 U2.11 U4.8 U5.8 | length 4150.9
  Top Layer w10: U1.6@4277.56,1373.8 U1.6@4277.56,1372.05 4311.02,1372.05
  Top Layer w12: v1(3999.59,1622.24) 3999.59,1625.41 4001.15,1626.97 U2.11@4048.71,1626.97 ; U1.8@4277.56,1423.23 4318.89,1423.23 4328.28,1432.62 4375.43,1432.62 4396.15,1411.9 ; 4311.02,1372.05 4356.29,1372.05 4396.15,1411.9 ; C4.1@4440.37,1462.13 C4.1@4438.5,1464 4438.5,1438.45 4413.05,1413 4397.24,1413 4396.15,1411.9
  Top Layer w20: U4.8@3341.54,2338.78 3429.64,2338.78 3507,2261.42 v1(3507,2188.78) 3431.81,2188.78 R19.2@3431.3,2189.29 3452.29,2189.29 ; 3757.31,1634.81 3757.31,1705.76 3837,1785.45 v1(3837,1815) 3822.87,1829.13 R4.2@3798,1829.13 ; v1(4328.45,1554.02) 4329.15,1554.72 4415.53,1554.72 4435.68,1534.56 R2.2@4435.68,1527 C4.1@4435.68,1464
  Bottom Layer w12: 3930,1944.32 3930,1872 4008.38,1793.62 4008.38,1631.54 3999.07,1622.24 v1(3999.59,1622.24)
  Bottom Layer w20: v1(3534,1635.11) 3534,1732.82 3469.25,1797.57 3469.25,2151.03 v1(3507,2188.78) 3595.22,2277 3904.97,2277 3990,2362.03 3990,2721.42 J2.1@3899.21,2812.2 ; v1(3837,1815) 3837,1817.5 3839.13,1819.62 3839.13,1888.24 3857.21,1906.32 3857.66,1906.32 3860.21,1908.87 3860.47,1908.87 3895.92,1944.32 3930,1944.32 4264.28,1944.32 4306.78,1901.83 4306.78,1575.69 v1(4328.45,1554.02)
5V: J2.2
12V: C17.1 C18.1 C20.1 D2.1 L1.1 Q2.5 Q2.6 Q2.7 Q2.8 Q2.9
  other v2: 2661.1,1972.8 2701.1,1972.8 2741.1,1972.8 2781.1,1972.8 2661.1,2012.8 2701.1,2012.8 2741.1,2012.8 2781.1,2012.8 2661.1,2052.8 2701.1,2052.8 2741.1,2052.8 2781.1,2052.8
BLSP: J1.15 R1.2 | length 169.1
  Top Layer w10: J1.15@4663.78,2148.82 4728,2213.04 R1.2@4728,2291.34
BTN_EC: J2.6
CPH: C9.1 U2.22 | length 130.8
  Top Layer w10: U2.22@4288.87,1831.69 U2.22@4292.73,1835.55 ; C9.1@4353,1840.32 C9.1@4353,1835.55 ; U2.22@4292.73,1835.55 C9.1@4353,1835.55 ; U2.22@4292.73,1835.55 C9.1@4353,1835.55
CPL: C9.2 U2.23 | length 73.5
  Top Layer w10: U2.23@4288.87,1857.28 4330.28,1857.28 4330.28,1857.46 4352.51,1879.69 C9.2@4353,1879.69
DIA_EN: J3.15 R13.1 | length 2485.7
  Top Layer w10: v1(4136.16,2231.69) 4136.16,2146.3 4176.46,2106 v1(4176.46,2023.97) ; v1(4200.66,2370) 4241.03,2370 4237.91,2373.12 4234.78,2376.25 R13.1@4246.53,2388
  Bottom Layer w10: J3.15@3199.21,1112.2 3043.62,1267.79 3043.62,1486.72 3105.01,1548.11 3661.39,1548.11 3736.37,1623.1 3736.37,1753.48 3724.48,1765.37 3723.76,1765.37 3721.38,1767.76 3721.38,1950.3 3787.72,2016.65 4169.13,2016.65 v1(4176.46,2023.97) ; v1(4136.16,2231.69) 4136.16,2336.96 4134,2339.12 4164.55,2369.67 4200.33,2369.67 v1(4200.66,2370)
DISABLE: J3.4 U2.9 | length 937.5
  Top Layer w10: v1(3852.76,1670.88) 3869.76,1687.87 3989.5,1687.87 3999.22,1678.15 U2.9@4048.71,1678.15
  Bottom Layer w10: J3.4@3799.21,1012.2 3750,1061.42 3750,1148.33 3863.47,1261.79 3863.47,1647.53 3852.76,1658.24 v1(3852.76,1670.88)
DISC: J3.17 Q3.1 R17.1 | length 1383.7
  Top Layer w10: v1(3708,1734) 3711,1734 3711,1681.87 Q3.1@3721.36,1671.51 ; R17.1@3711.37,1620 3715.38,1624.02 Q3.1@3715.38,1671.51
  Bottom Layer w10: J3.17@3099.21,1112.2 3099.21,1181.9 3025.75,1255.36 3025.75,1494.13 3097.61,1565.99 3653.99,1565.99 3708,1620 v1(3708,1734)
DOWN: J2.9
DVDD: C7.1 U2.1 | length 96.3
  Top Layer w10: C7.1@3996,1957.31 4048.71,1904.6 U2.1@4048.71,1882.87
EC: C22.1 J1.13 Q3.3 Q4.3 R16.2 | length 2818.4
  Top Layer w10: C22.1@3646.5,1446 3655.5,1455 v1(3700.69,1455)
  Top Layer w20: R16.2@3646.5,1389 C22.1@3646.5,1446
  Bottom Layer w10: v1(3700.69,1455) 3700.69,1507.44 3790,1596.75 3790,1600.88 3790.36,1601.25 3790.36,1786.64 v1(3783,1794)
  Bottom Layer w20: v1(3585,1707.6) 3585,1721.24 3497.12,1809.12 3497.12,2129.12 3616.45,2248.45 3946.45,2248.45 4180.07,2482.07 4662.07,2482.07 4715.29,2428.85 4715.29,2240.29 4686.88,2211.88 4635.88,2211.88 4605,2181 4605,2120.41 4663.78,2061.63 J1.13@4663.78,2048.82
EC_PWM: J3.7 R21.1 | length 395.6
  Top Layer w10: R21.1@3353.64,1263 3353.64,1239.36 3449.58,1143.42 3449.58,1089.42 3477.62,1061.38 3548.39,1061.38 J3.7@3599.21,1112.2
EN_1HB16: J3.11 R10.1 | length 2224.7
  Top Layer w10: v1(4238.13,1978.8) 4263.93,1953 R10.1@4292.06,1953
  Bottom Layer w10: J3.11@3399.21,1112.2 3294.99,1216.43 3148.45,1216.43 3079.37,1285.51 3079.37,1471.92 3119.82,1512.36 3676.2,1512.36 3772.49,1608.66 3772.49,1768.13 3772.28,1768.13 3757.13,1783.28 3757.13,1935.5 3799.76,1978.13 4237.45,1978.13 v1(4238.13,1978.8)
EN_1028: J3.5 U4.2 | length 2405.3
  Top Layer w10: v4(2920.43,947.16) 3611.13,947.16 3629.97,966 3648.39,984.43 3648.39,1061.38 J3.5@3699.21,1112.2 ; v1(2988,2283) 3129.06,2283 U4.2@3134.84,2288.78
  Bottom Layer w10: v4(2920.43,947.16) 2920.43,1226.1 2928,1233.67 2956.25,1261.92 2956.25,2251.25 v1(2988,2283)
EN_8873: J3.1 U2.7 | length 851.8
  Top Layer w10: v1@3873,1750 3893.67,1729.33 U2.7@4048.71,1729.33
  Bottom Layer w10: v1(3872.68,1750.23) 3899.21,1723.69 J3.1@3899.21,1112.2 J3.1@3917.75,1112.2
FM1: J1.5 U2.18 U2.19 | length 414.8
  Top Layer w35: 4290,1742.15 4346.54,1742.15 4363.69,1725 4418.79,1725
  Top Layer w45: 4418.79,1725 4455,1725
  Top Layer w50: 4455,1725 4591.61,1725 4663.78,1652.83 J1.5@4663.78,1648.82
FM2: J1.6 U2.14 U2.15 | length 1075.8
  Top Layer w35: 4303.83,1640.7 4358.7,1640.7 4373.36,1655.36 4410,1655.48 ; 4457.66,1655.48 4457.78,1655.36
  Top Layer w45: 4422,1655.48 4457.66,1655.48
  Top Layer w50: 4457.78,1655.36 4542.79,1655.36 4572.33,1625.82 v1(4572.33,1539)
  Bottom Layer w45: v1@4572.33,1561.37 4572.33,1421.67 4614,1380 4806.35,1380 4843.26,1416.91 4843.26,1579.74 4774.18,1648.82 J1.6@4763.78,1648.82
  other v1: 4572,1568.74
FOLD: J2.16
